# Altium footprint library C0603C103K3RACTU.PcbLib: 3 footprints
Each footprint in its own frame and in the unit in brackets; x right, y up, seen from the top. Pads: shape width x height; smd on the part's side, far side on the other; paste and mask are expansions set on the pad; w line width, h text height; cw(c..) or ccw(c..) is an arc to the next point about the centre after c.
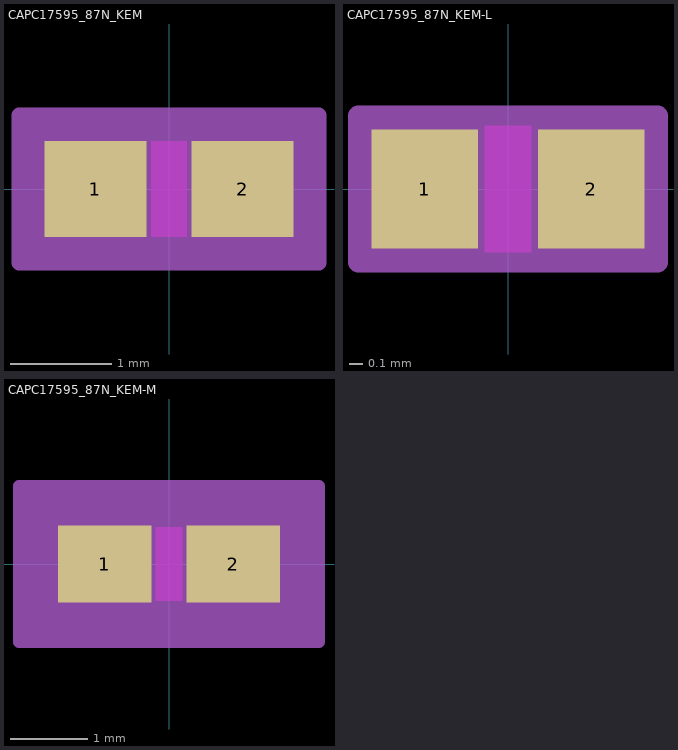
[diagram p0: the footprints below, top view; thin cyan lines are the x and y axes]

## CAPC17595_87N_KEM [mm]
pads (2):
  rect 1.006x0.95 smd paste+0 mask+0: 1(-0.728,0) 2(0.728,0)
Top Layer keep-out:
  region: -0.174,-0.424 -0.174,0.424 0.174,0.424 0.174,-0.424
Keep-Out Layer:
  region: -0.174,-0.475 -0.174,0.475 0.174,0.475 0.174,-0.475
Mechanical 13:
  lines w0.025: -0.875,-0.475 -0.875,0.475 ; -0.875,-0.475 -0.375,-0.475 -0.375,0.475 -0.875,0.475 ; -0.875,-0.475 0.875,-0.475 ; -0.875,-0.475 -0.875,0.475 ; -0.875,0.475 0.875,0.475 ; 0.875,-0.475 0.375,-0.475 0.375,0.475 0.875,0.475 ; 0.875,-0.475 0.875,0.475 ; 0.875,-0.475 0.875,0.475
Mechanical 15:
  region: 1.485,-0.729 -1.485,-0.729 -1.485,0.729 1.485,0.729
  lines w0.152: -1.485,-0.729 -1.485,0.729 1.485,0.729 1.485,-0.729 -1.485,-0.729
3D body "CAPC17595_87N_KEM.step": height 0.87, standoff 0, extent -0.875,-0.475 0.875,0.475

## CAPC17595_87N_KEM-L [mm]
pads (2):
  rect 0.802x0.899 smd paste+0 mask+0: 1(-0.626,0) 2(0.626,0)
Top Layer keep-out:
  region: -0.174,-0.424 -0.174,0.424 0.174,0.424 0.174,-0.424
Keep-Out Layer:
  region: -0.174,-0.475 -0.174,0.475 0.174,0.475 0.174,-0.475
Mechanical 13:
  lines w0.025: -0.875,-0.475 -0.875,0.475 ; -0.875,-0.475 -0.375,-0.475 -0.375,0.475 -0.875,0.475 ; -0.875,-0.475 0.875,-0.475 ; -0.875,-0.475 -0.875,0.475 ; -0.875,0.475 0.875,0.475 ; 0.875,-0.475 0.375,-0.475 0.375,0.475 0.875,0.475 ; 0.875,-0.475 0.875,0.475 ; 0.875,-0.475 0.875,0.475
Mechanical 15:
  region: 1.129,-0.551 -1.129,-0.551 -1.129,0.551 1.129,0.551
  lines w0.152: -1.129,-0.551 -1.129,0.551 1.129,0.551 1.129,-0.551 -1.129,-0.551
3D body "CAPC17595_87N_KEM.step": height 0.87, standoff 0, extent -0.875,-0.475 0.875,0.475

## CAPC17595_87N_KEM-M [mm]
pads (2):
  rect 1.209x1.001 smd paste+0 mask+0: 1(-0.829,0) 2(0.829,0)
Top Layer keep-out:
  region: -0.174,-0.424 -0.174,0.424 0.174,0.424 0.174,-0.424
Keep-Out Layer:
  region: -0.174,-0.475 -0.174,0.475 0.174,0.475 0.174,-0.475
Mechanical 13:
  lines w0.025: -0.875,-0.475 -0.875,0.475 ; -0.875,-0.475 -0.375,-0.475 -0.375,0.475 -0.875,0.475 ; -0.875,-0.475 0.875,-0.475 ; -0.875,-0.475 -0.875,0.475 ; -0.875,0.475 0.875,0.475 ; 0.875,-0.475 0.375,-0.475 0.375,0.475 0.875,0.475 ; 0.875,-0.475 0.875,0.475 ; 0.875,-0.475 0.875,0.475
Mechanical 15:
  region: 1.942,-1.008 -1.942,-1.008 -1.942,1.008 1.942,1.008
  lines w0.152: -1.942,-1.008 -1.942,1.008 1.942,1.008 1.942,-1.008 -1.942,-1.008
3D body "CAPC17595_87N_KEM.step": height 0.87, standoff 0, extent -0.875,-0.475 0.875,0.475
